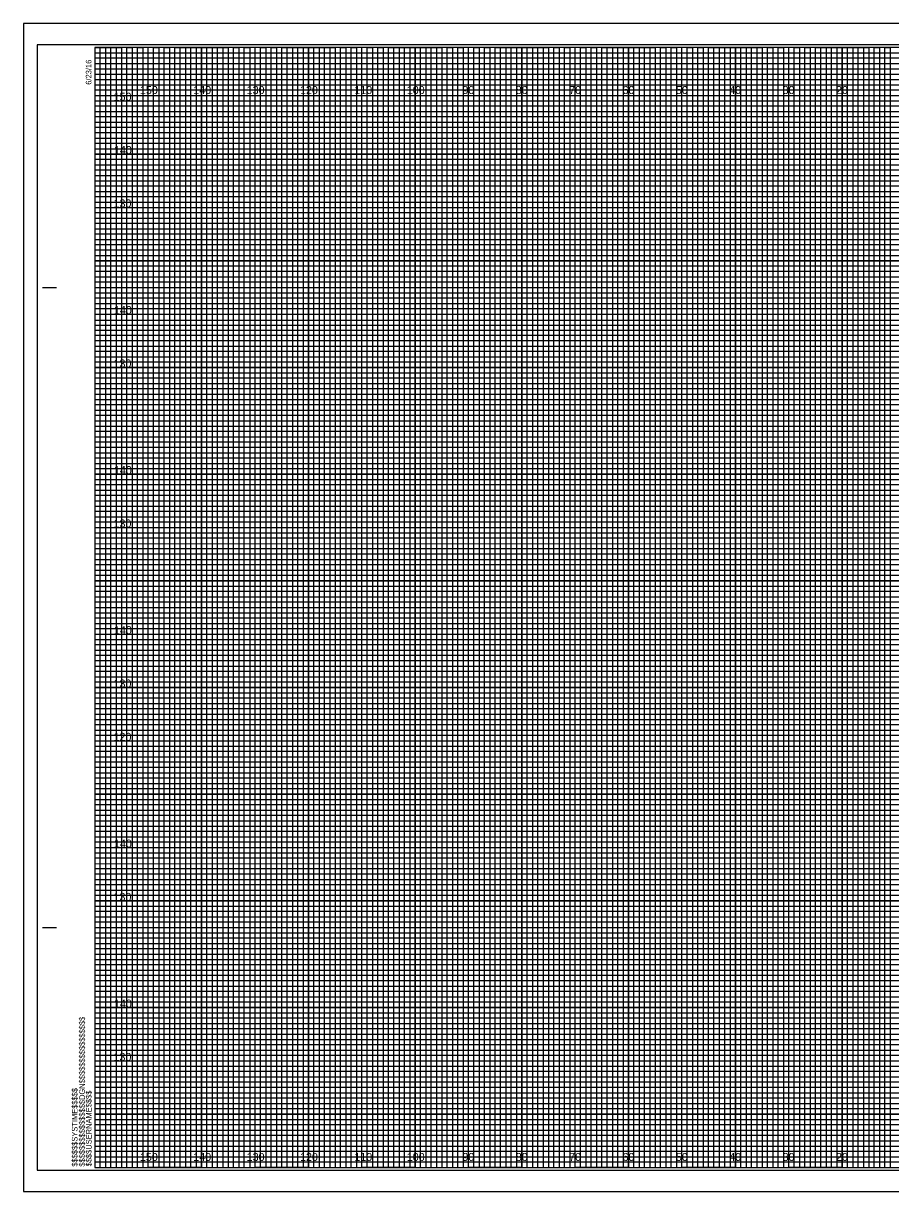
# Model space of a CAD drawing. Extents: x -13 to 323, y -5 to 215.
# Drawn here: x -13.4 to 149.1, y -4.5 to 214.5 of the extents above; entities that cross this region are included whole.
import ezdxf

# ---------------------------------------------------------------- set-up
doc = ezdxf.new("R2010")
doc.units = 0
for name, color, linetype in [('Exist Cross Section Cell', 7, 'Continuous'), ('Exist XS Center Line Elevation Label', 7, 'Continuous'), ('Exist XS Ground Line', 7, 'Continuous'), ('Prop CMT Pvmt Course 1 Wedge', 7, 'Continuous'), ('Prop CMT Pvmt Course 2', 7, 'Continuous'), ('Prop CMT Pvmt Course 2 Wedge', 7, 'Continuous'), ('Prop CMT Pvmt Course 3', 7, 'Continuous'), ('Prop CMT Shld Paved Course 1', 7, 'Continuous'), ('Prop CMT Shld Paved Course 2', 7, 'Continuous'), ('Prop CMT Subgrade Earthwork', 7, 'Continuous'), ('Scratch_Level_0', 7, 'Continuous')]:
    doc.layers.add(name, color=color, linetype=linetype)

msp = doc.modelspace()

# ---------------------------------------------------------------- linework, layer by layer
at = {"layer": 'Exist XS Center Line Elevation Label'}
for points in [[(0, 210), (5, 210), (5, 0), (15, 0), (15, 210), (25, 210), (25, 0), (35, 0), (35, 210), (45, 210), (45, 0), (55, 0), (55, 210), (65, 210), (65, 0), (75, 0), (75, 210), (85, 210), (85, 0), (95, 0), (95, 210), (105, 210), (105, 0), (115, 0), (115, 210), (125, 210), (125, 0), (135, 0), (135, 210), (145, 210), (145, 0), (155, 0)], [(0, 205), (275, 205)], [(0, 185), (320, 185), (320, 195), (0, 195)], [(0, 165), (320, 165), (320, 175), (0, 175)], [(0, 145), (320, 145), (320, 155), (0, 155)], [(0, 125), (320, 125), (320, 135), (0, 135)], [(0, 105), (320, 105), (320, 115), (0, 115)], [(0, 85), (320, 85), (320, 95), (0, 95)], [(0, 65), (320, 65), (320, 75), (0, 75)], [(0, 45), (320, 45), (320, 55), (0, 55)], [(0, 25), (320, 25), (320, 35), (0, 35)], [(0, 5), (320, 5), (320, 15), (0, 15)]]:
    msp.add_lwpolyline(points, dxfattribs=at)
at = {"layer": 'Exist XS Ground Line'}
for p, q in [((10, 210), (0, 210)), ((10, 0), (10, 210)), ((30, 210), (20, 210)), ((20, 210), (20, 0)), ((30, 0), (30, 210)), ((50, 210), (40, 210)), ((40, 210), (40, 0)), ((50, 0), (50, 210)), ((70, 210), (60, 210)), ((60, 210), (60, 0)), ((70, 0), (70, 210)), ((90, 210), (80, 210)), ((80, 210), (80, 0)), ((90, 0), (90, 210)), ((110, 210), (100, 210)), ((100, 210), (100, 0)), ((110, 0), (110, 210)), ((130, 210), (120, 210)), ((120, 210), (120, 0)), ((130, 0), (130, 210)), ((150, 210), (140, 210)), ((140, 210), (140, 0)), ((20, 0), (10, 0)), ((40, 0), (30, 0)), ((60, 0), (50, 0)), ((80, 0), (70, 0)), ((100, 0), (90, 0)), ((120, 0), (110, 0)), ((140, 0), (130, 0))]:
    msp.add_line(p, q, dxfattribs=at)
for points in [[(0, 200), (320, 200), (320, 190), (0, 190)], [(0, 180), (320, 180), (320, 170), (0, 170)], [(0, 160), (320, 160), (320, 150), (0, 150)], [(0, 140), (320, 140), (320, 130), (0, 130)], [(0, 120), (320, 120), (320, 110), (0, 110)], [(0, 100), (320, 100), (320, 90), (0, 90)], [(0, 80), (320, 80), (320, 70), (0, 70)], [(0, 60), (320, 60), (320, 50), (0, 50)], [(0, 40), (320, 40), (320, 30), (0, 30)], [(0, 20), (320, 20), (320, 10), (0, 10)]]:
    msp.add_lwpolyline(points, dxfattribs=at)
at = {"layer": 'Prop CMT Pvmt Course 1 Wedge'}
for p, q in [((323.3, 214.5), (-13.4, 214.5)), ((-13.4, 214.5), (-13.4, -4.5)), ((-13.4, -4.5), (323.3, -4.5))]:
    msp.add_line(p, q, dxfattribs=at)
at = {"layer": 'Prop CMT Pvmt Course 2'}
msp.add_lwpolyline([(-13.4, -4.5), (323.3, -4.5), (323.3, 214.5), (-13.4, 214.5)], close=True, dxfattribs=at)
at = {"layer": 'Prop CMT Pvmt Course 3'}
msp.add_lwpolyline([(-10.8, -0.5), (322.4, -0.5), (322.4, 210.5), (-10.8, 210.5)], close=True, dxfattribs=at)
at = {"layer": 'Prop CMT Shld Paved Course 1'}
for p, q in [((-9.8, 165), (-7.3, 165)), ((-9.7, 165), (-7.2, 165)), ((-9.8, 45), (-7.3, 45)), ((-9.7, 45), (-7.2, 45)), ((0, 0), (0, 0)), ((0, 0), (0, 0)), ((0, 0), (0, 0)), ((0, 0), (0, 0)), ((0, 0), (0, 0)), ((0, 0), (0, 0)), ((0, 0), (0, 0))]:
    msp.add_line(p, q, dxfattribs=at)
msp.add_lwpolyline([(320, 210), (0, 210), (0, 0), (320, 0)], close=True, dxfattribs=at)
at = {"layer": 'Prop CMT Shld Paved Course 2'}
for points in [[(0, 0), (1, 0), (1, 210), (2, 210), (2, 0)], [(2, 0), (3, 0), (3, 210), (4, 210), (4, 0)], [(5, 0), (6, 0), (6, 210), (7, 210), (7, 0)], [(7, 0), (8, 0), (8, 210), (9, 210), (9, 0)], [(10, 0), (11, 0), (11, 210), (12, 210), (12, 0)], [(12, 0), (13, 0), (13, 210), (14, 210), (14, 0)], [(15, 0), (16, 0), (16, 210), (17, 210), (17, 0)], [(17, 0), (18, 0), (18, 210), (19, 210), (19, 0)], [(20, 0), (21, 0), (21, 210), (22, 210), (22, 0)], [(22, 0), (23, 0), (23, 210), (24, 210), (24, 0)], [(25, 0), (26, 0), (26, 210), (27, 210), (27, 0)], [(27, 0), (28, 0), (28, 210), (29, 210), (29, 0)], [(30, 0), (31, 0), (31, 210), (32, 210), (32, 0)], [(32, 0), (33, 0), (33, 210), (34, 210), (34, 0)], [(35, 0), (36, 0), (36, 210), (37, 210), (37, 0)], [(37, 0), (38, 0), (38, 210), (39, 210), (39, 0)], [(40, 0), (41, 0), (41, 210), (42, 210), (42, 0)], [(42, 0), (43, 0), (43, 210), (44, 210), (44, 0)], [(45, 0), (46, 0), (46, 210), (47, 210), (47, 0)], [(47, 0), (48, 0), (48, 210), (49, 210), (49, 0)], [(50, 0), (51, 0), (51, 210), (52, 210), (52, 0)], [(52, 0), (53, 0), (53, 210), (54, 210), (54, 0)], [(55, 0), (56, 0), (56, 210), (57, 210), (57, 0)], [(57, 0), (58, 0), (58, 210), (59, 210), (59, 0)], [(60, 0), (61, 0), (61, 210), (62, 210), (62, 0)], [(62, 0), (63, 0), (63, 210), (64, 210), (64, 0)], [(65, 0), (66, 0), (66, 210), (67, 210), (67, 0)], [(67, 0), (68, 0), (68, 210), (69, 210), (69, 0)], [(70, 0), (71, 0), (71, 210), (72, 210), (72, 0)], [(72, 0), (73, 0), (73, 210), (74, 210), (74, 0)], [(75, 0), (76, 0), (76, 210), (77, 210), (77, 0)], [(77, 0), (78, 0), (78, 210), (79, 210), (79, 0)], [(80, 0), (81, 0), (81, 210), (82, 210), (82, 0)], [(82, 0), (83, 0), (83, 210), (84, 210), (84, 0)], [(85, 0), (86, 0), (86, 210), (87, 210), (87, 0)], [(87, 0), (88, 0), (88, 210), (89, 210), (89, 0)], [(90, 0), (91, 0), (91, 210), (92, 210), (92, 0)], [(92, 0), (93, 0), (93, 210), (94, 210), (94, 0)], [(95, 0), (96, 0), (96, 210), (97, 210), (97, 0)], [(97, 0), (98, 0), (98, 210), (99, 210), (99, 0)], [(100, 0), (101, 0), (101, 210), (102, 210), (102, 0)], [(102, 0), (103, 0), (103, 210), (104, 210), (104, 0)], [(105, 0), (106, 0), (106, 210), (107, 210), (107, 0)], [(107, 0), (108, 0), (108, 210), (109, 210), (109, 0)], [(110, 0), (111, 0), (111, 210), (112, 210), (112, 0)], [(112, 0), (113, 0), (113, 210), (114, 210), (114, 0)], [(115, 0), (116, 0), (116, 210), (117, 210), (117, 0)], [(117, 0), (118, 0), (118, 210), (119, 210), (119, 0)], [(120, 0), (121, 0), (121, 210), (122, 210), (122, 0)], [(122, 0), (123, 0), (123, 210), (124, 210), (124, 0)], [(125, 0), (126, 0), (126, 210), (127, 210), (127, 0)], [(127, 0), (128, 0), (128, 210), (129, 210), (129, 0)], [(130, 0), (131, 0), (131, 210), (132, 210), (132, 0)], [(132, 0), (133, 0), (133, 210), (134, 210), (134, 0)], [(135, 0), (136, 0), (136, 210), (137, 210), (137, 0)], [(137, 0), (138, 0), (138, 210), (139, 210), (139, 0)], [(140, 0), (141, 0), (141, 210), (142, 210), (142, 0)], [(142, 0), (143, 0), (143, 210), (144, 210), (144, 0)], [(145, 0), (146, 0), (146, 210), (147, 210), (147, 0)], [(147, 0), (148, 0), (148, 210), (149, 210), (149, 0)]]:
    msp.add_lwpolyline(points, dxfattribs=at)
at = {"layer": 'Prop CMT Subgrade Earthwork'}
for p, q in [((10, 0), (10, 210)), ((20, 0), (20, 210)), ((30, 0), (30, 210)), ((40, 0), (40, 210)), ((50, 0), (50, 210)), ((60, 0), (60, 210)), ((70, 0), (70, 210)), ((80, 0), (80, 210)), ((90, 0), (90, 210)), ((100, 0), (100, 210)), ((110, 0), (110, 210)), ((120, 0), (120, 210)), ((130, 0), (130, 210)), ((140, 0), (140, 210)), ((0, 200), (320, 200)), ((0, 190), (320, 190)), ((0, 180), (320, 180)), ((0, 170), (320, 170)), ((0, 160), (320, 160)), ((0, 150), (320, 150)), ((0, 140), (320, 140)), ((0, 130), (320, 130)), ((0, 120), (320, 120)), ((0, 110), (320, 110)), ((0, 100), (320, 100)), ((0, 90), (320, 90)), ((0, 80), (320, 80)), ((0, 70), (320, 70)), ((0, 60), (320, 60)), ((0, 50), (320, 50)), ((0, 40), (320, 40)), ((0, 30), (320, 30)), ((0, 20), (320, 20)), ((0, 10), (320, 10))]:
    msp.add_line(p, q, dxfattribs=at)
at = {"layer": 'Scratch_Level_0'}
for p, q in [((0, 209), (260, 209)), ((260, 207.98), (0, 207.98)), ((0, 207.98), (0, 207)), ((0, 207), (260, 207)), ((260, 205.89), (0, 205.89)), ((0, 205.89), (0, 204)), ((0, 204), (320, 204))]:
    msp.add_line(p, q, dxfattribs=at)
for points in [[(0, 203), (270, 203), (320, 203), (320, 202), (0, 202)], [(0, 201), (320, 201), (320, 199), (0, 199)], [(0, 198), (320, 198), (320, 197), (0, 196.98)], [(0, 196), (320, 196), (320, 194), (0, 194)], [(0, 193), (320, 193), (320, 192), (0, 192)], [(0, 191), (320, 191), (320, 189), (0, 189)], [(0, 188), (320, 188), (320, 187), (0, 187)], [(0, 186), (320, 186), (320, 184), (0, 184)], [(0, 183), (320, 183), (320, 182), (0, 182)], [(0, 181), (320, 181), (320, 179), (0, 179)], [(0, 178), (320, 178), (320, 177), (0, 177)], [(0, 176), (320, 176), (320, 173.95), (320, 173), (320, 172), (0, 172)], [(0, 174), (320, 174), (320, 173), (0, 173)], [(0, 171), (320, 171), (320, 169), (0, 169.03)], [(0, 169.03), (320, 169), (320, 168), (0, 168)], [(0, 167), (320, 167), (320, 166), (0, 166)], [(0, 164), (320, 164), (320, 163), (0, 163)], [(0, 162), (320, 162), (320, 161), (0, 161)], [(-0.07, 158.89), (320, 158.89), (320, 157.88), (-0.07, 157.88)], [(0, 157), (320, 157), (320, 156), (0, 156)], [(0, 154), (320, 154), (320, 153), (0, 153)], [(0, 152), (320, 152), (320, 151), (0, 151)], [(0, 149), (320, 149), (320, 148), (0, 148)], [(0, 147), (320, 147), (320, 146), (0, 146)], [(0, 144), (320, 144), (320, 143), (0, 143)], [(0, 142), (320, 142), (320, 141), (0, 141)], [(0, 139), (320, 139), (319.99, 137.98), (0, 138)], [(0, 137), (320, 137), (320, 136), (0, 136)], [(0, 134), (320, 134), (320, 133), (0, 133)], [(0, 132), (320, 132), (320, 131), (0, 131)], [(0, 129), (320, 129), (320, 128), (0, 128)], [(0, 127), (320, 127), (320, 126), (0, 126)], [(0, 124), (320, 124), (320, 123), (0, 123)], [(0, 122), (320, 122), (320, 121), (0, 121)], [(0, 119), (320, 119), (320, 118), (0, 118)], [(0, 116.99), (320.07, 116.91), (320, 116), (0, 116)], [(0, 114), (320, 114), (320, 113), (0, 113)], [(0, 112), (320, 112), (320, 111), (0, 111)], [(0, 109), (320, 109), (320, 108), (0, 108)], [(0, 107), (320, 107), (320, 106), (0, 106)], [(0, 104), (320, 104), (320, 103), (0, 103)], [(0, 102), (320, 102), (320, 101), (0, 101)], [(0, 99), (320, 99), (320, 98), (0, 98)], [(0, 97), (320, 97), (320, 96), (0, 96)], [(0, 94), (320, 94), (320, 93), (0, 93)], [(0, 92), (320, 92), (320, 91), (0, 91)], [(0, 89), (320, 89), (320, 88), (0, 88)], [(0, 87), (320, 87), (320, 86), (0, 86)], [(0, 84), (320, 84), (320, 83), (0, 83)], [(0, 82), (320, 82), (320, 81), (0, 81)], [(0, 79), (320, 79), (319.99, 77.98), (0, 78)], [(0, 77), (320, 77), (320, 76), (0, 76)], [(0, 74), (320, 74), (320, 73), (0, 73)], [(0, 72), (320, 72), (320, 71), (0, 71)], [(0, 69), (320, 69), (320, 68), (0, 68)], [(0, 67), (320, 67), (320, 66), (0, 66)], [(0, 64), (320, 64), (320, 63), (0, 63)], [(0, 62), (320, 62), (320, 61), (0, 61)], [(0, 59), (320, 59), (320, 58), (0, 58)], [(0, 56.99), (320.07, 56.91), (320, 56), (0, 56)], [(0, 54), (320, 54), (320, 53), (0, 53)], [(0, 52), (320, 52), (320, 51), (0, 51)], [(0, 49), (320, 49), (320, 48), (0, 48)], [(0, 47), (320, 47), (320, 46), (0, 46)], [(0, 44), (320, 44), (320, 43), (0, 43)], [(0, 42), (320, 42), (320, 41), (0, 41)], [(0, 39), (320, 39), (320, 38), (0, 38)], [(0, 37), (320, 37), (320, 36), (0, 36)], [(0, 34), (320, 34), (320, 33), (0, 33)], [(0, 32), (320, 32), (320, 31), (0, 31)], [(0, 29), (320, 29), (320, 28), (0, 28)], [(0, 27), (320, 27), (320, 26), (0, 26)], [(0, 24), (320, 24), (320, 23), (0, 23)], [(0, 22), (320, 22), (320, 21), (0, 21)], [(0, 19), (320, 19), (320, 18), (0, 18)], [(0, 17), (320, 17), (320, 16), (0, 16)], [(0, 14), (320, 14), (320, 13), (0, 13)], [(0, 12), (320, 12), (320, 11), (0, 11)], [(0, 9), (320, 9), (320, 8), (0, 8)], [(0, 7), (320, 7), (320, 6), (0, 6)], [(0, 4), (320, 4), (320, 3), (0, 3)], [(0, 2), (320, 2), (320, 1), (0, 1)]]:
    msp.add_lwpolyline(points, dxfattribs=at)

# ---------------------------------------------------------------- texts
at = {"layer": 'Exist Cross Section Cell'}
for s, p in [('150', (8.44, 201.25)), ('140', (18.44, 201.25)), ('130', (28.44, 201.25)), ('120', (38.44, 201.25)), ('110', (48.62, 201.25)), ('100', (58.44, 201.25)), ('90', (68.86, 201.25)), ('80', (78.86, 201.25)), ('70', (88.86, 201.25)), ('60', (98.86, 201.25)), ('50', (108.86, 201.25)), ('40', (118.86, 201.25)), ('30', (128.86, 201.25)), ('20', (138.86, 201.25)), ('150', (8.44, 1.25)), ('140', (18.44, 1.25)), ('130', (28.44, 1.25)), ('120', (38.44, 1.25)), ('110', (48.62, 1.25)), ('100', (58.44, 1.25)), ('90', (68.86, 1.25)), ('80', (78.86, 1.25)), ('70', (88.86, 1.25)), ('60', (98.86, 1.25)), ('50', (108.86, 1.25)), ('40', (118.86, 1.25)), ('30', (128.86, 1.25)), ('20', (138.86, 1.25))]:
    msp.add_text(s, height=1.5, dxfattribs=at).set_placement(p)
at = {"layer": 'Prop CMT Pvmt Course 2 Wedge'}
for s, p in [('150', (3.52, 200)), ('140', (3.57, 190)), ('130', (3.49, 180)), ('140', (3.57, 160)), ('130', (3.49, 150)), ('140', (3.57, 130)), ('130', (3.49, 120)), ('140', (3.57, 100)), ('130', (3.49, 90)), ('120', (3.5, 80)), ('140', (3.57, 60)), ('130', (3.49, 50)), ('140', (3.57, 30)), ('130', (3.49, 20))]:
    msp.add_text(s, height=1.5, dxfattribs=at).set_placement(p)
at = {"layer": 'Prop CMT Shld Paved Course 1'}
for s, p in [('6/23/16', (-0.65, 203)), ('$$$$$$$$$$$$$$$$DGN$$$$$$$$$$$$$$$$', (-1.88, 0.18)), ('$$$$$$SYSTIME$$$$$', (-3.26, 0.18)), ('$$$$USERNAME$$$$', (-0.62, 0.23))]:
    msp.add_text(s, height=1.05, rotation=90, dxfattribs=at).set_placement(p)

doc.saveas('drawing.dxf')
